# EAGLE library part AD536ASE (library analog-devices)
ANALOG DEVICES
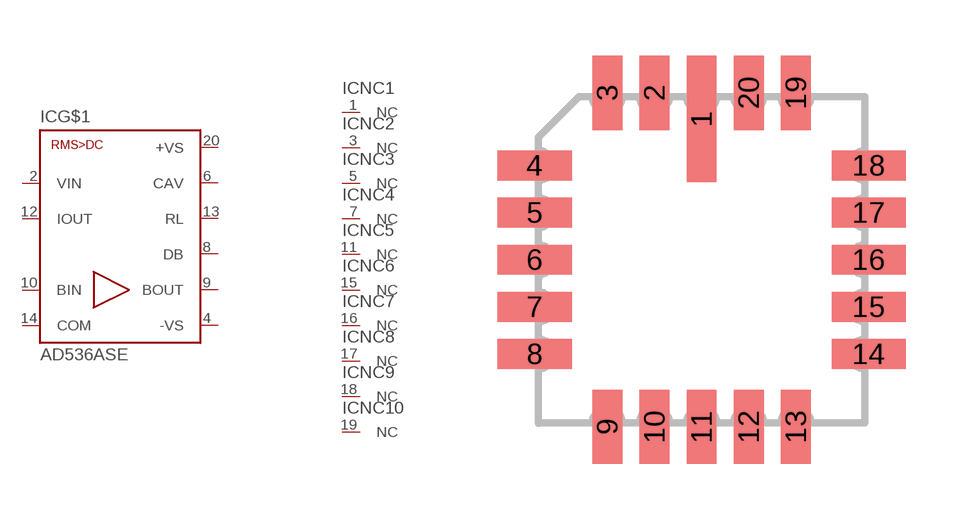
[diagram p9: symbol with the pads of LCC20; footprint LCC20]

Designator prefix IC; gates G$1=AD536 NC1=NC NC2=NC NC3=NC NC4=NC NC5=NC NC6=NC NC7=NC NC8=NC NC9=NC NC10=NC

## AD536ASE (OC_FARNELL: unknown; OC_NEWARK: unknown)  [LCC20]
1  NC1:NC  nc
2  G$1:VIN  in
3  NC2:NC  nc
4  G$1:-VS  pwr
5  NC3:NC  nc
6  G$1:CAV  out
7  NC4:NC  nc
8  G$1:DB  out
9  G$1:BOUT  out
10  G$1:BIN  in
11  NC5:NC  nc
12  G$1:IOUT  out
13  G$1:RL  pas
14  G$1:COM  pwr
15  NC6:NC  nc
16  NC7:NC  nc
17  NC8:NC  nc
18  NC9:NC  nc
19  NC10:NC  nc
20  G$1:+VS  pwr

## Footprint LCC20 (pad centres in mm)
PLASTIC LEADED CHIP CARRIER
smd 0.8 x 3.4: 1 0,3.8
smd 0.8 x 2: 2 -1.27,4.5; 3 -2.54,4.5; 9 -2.54,-4.5; 10 -1.27,-4.5; 11 0,-4.5; 12 1.27,-4.5; 13 2.54,-4.5; 19 2.54,4.5; 20 1.27,4.5
smd 2 x 0.8: 4 -4.5,2.54; 5 -4.5,1.27; 6 -4.5,0; 7 -4.5,-1.27; 8 -4.5,-2.54; 14 4.5,-2.54; 15 4.5,-1.27; 16 4.5,0; 17 4.5,1.27; 18 4.5,2.54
